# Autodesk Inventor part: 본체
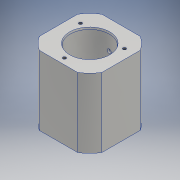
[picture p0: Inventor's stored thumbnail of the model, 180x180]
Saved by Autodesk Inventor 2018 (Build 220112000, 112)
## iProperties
Created: 2020-02
Part Number: 본체
Material: 알루미늄 6061
Document SubType Name: Modeling
Designer: Administrator
Density: 2.7 g/cm^3
Appearance: 알루미늄 - 평지
Mass: 538.447 g
Surface Area: 342.316 cm^2
Volume: 199.425 cm^3
Author: Administrator
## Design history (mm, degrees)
sketch "스케치1"
  geometry: L1 (-19.551, -32)-(19.551, -32); L2 (32, -19.551)-(32, 19.551); L3 (19.551, 32)-(-19.551, 32); L4 (-32, 19.551)-(-32, -19.551); L5 (-32, -32)-(32, 32); L6 (32, -32)-(-32, 32); A1 r 37.5 centre (0, 0) between (-19.551, 32) and (-32, 19.551); A2 r 37.5 centre (0, 0) between (-32, -19.551) and (-19.551, -32); A3 r 37.5 centre (0, 0) between (19.551, -32) and (32, -19.551); A4 r 37.5 centre (0, 0) between (32, 19.551) and (19.551, 32); 1 further point
  constraints: 12 end point, 8 point on circle, 4 centre point, 2 midpoint, 2 parallel, 2 perpendicular, 1 coincident, 1 horizontal
  dimensions: "d1" = 64 distance of L5.end L6.end; "d2" = 64 distance of L6.start L5.end; "d3" = 37.5 radius of A4; "d4" = 37.5 radius of A3; "d5" = 37.5 radius of A2; "d6" = 37.5 radius of A1; "d7" = 45 deg angle of L6 L2; "d8" = 64 distance between parallel lines of L2 L4; "d9" = 64 distance between parallel lines of L3 L1; "d10" = 32 distance from line of point (0, 0) L2; "d11" = 32 distance from line of point (0, 0) L3; "d12" = 0 distance from line of L5.end L2; "d13" = 64 distance from line of L5.start L2
extrude "돌출1" new body sketch "스케치1" distance "d14" = 71; taper "d15" = 0 deg
sketch "스케치2"
  geometry: C1 r 14 at (0, 0); 1 further point
  constraints: 1 centre point, 1 coincident
  dimensions: "d16" = 28 diameter of C1
extrude "돌출2" join sketch "스케치2" distance "d17" = 12; taper "d18" = 0 deg
sketch "스케치3"
  geometry: C1 r 20 at (0, 0); 1 further point
  constraints: 1 centre point, 1 coincident
  dimensions: "d19" = 40 diameter of C1
extrude "돌출3" cut sketch "스케치3" distance "d20" = 62; taper "d21" = 0 deg
sketch "스케치4"
  geometry: C1 r 2 at (0, 0); 1 further point
  constraints: 1 centre point, 1 coincident
  dimensions: "d22" = 4 diameter of C1
extrude "돌출4" cut sketch "스케치4" distance "d23" = 62; taper "d24" = 0 deg
sketch "스케치5"
  geometry: C1 r 2 at (0, 0) reference; 2 further points
  constraints: 1 coincident
hole "구멍1" sketch "스케치5" at (0, 0) diameter "d25" = 8.376; stored, may be unused: countersink angle "d29" = 90 deg, drill point angle "d31" = 118 deg; dims "d26" = 14, "d27" = 4, "d28" = 2, "d30" = 17
sketch "스케치6"
  geometry: L1 (39.102, -71)-(0, -71) reference; L2 (-12.449, 0)-(-12.449, -71) reference; C1 r 2 at (19.551, -54); 1 further point
  constraints: 1 centre point
  dimensions: "d32" = 17 distance from line of L1 C1.centre; "d33" = 32 distance from line of L2 C1.centre; "d34" = 4 diameter of C1
extrude "돌출5" cut sketch "스케치6" distance "d35" = 20; taper "d36" = 0 deg
sketch "스케치7"
  geometry: C1 r 2 at (19.551, -54) reference; 2 further points
  constraints: 1 coincident
hole "구멍2" sketch "스케치7" at (19.551, -54) diameter "d37" = 8.376; stored, may be unused: countersink angle "d41" = 90 deg, drill point angle "d43" = 118 deg; dims "d38" = 6, "d39" = 4, "d40" = 2, "d42" = 9
sketch "스케치8"
  geometry: C1 r 2 at (0, 0) reference; A1 r 26 centre (0, 0) between (0, 26) and (26, 0); 3 further points
  constraints: 4 point on circle, 1 centre point, 1 coincident
  dimensions: "d44" = 52 diameter of A1
hole "구멍3" sketch "스케치8" at (0, 26), (26, 0), (0, -26), (-26, 0) diameter "d45" = 3.242; stored, may be unused: countersink angle "d49" = 90 deg, drill point angle "d51" = 118 deg; dims "d46" = 10, "d47" = 4, "d48" = 2, "d50" = 12
sketch "스케치10"
  geometry: L1 (0, 26)-(0, -26); L2 (0, 0)-(22.517, 13); L3 (0, 0)-(-22.517, 13); C1 r 2 at (0, 0) reference; C2 r 1.621 at (0, 26) reference; C3 r 4.188 at (0, 0) reference; C4 r 14 at (0, 0) reference; A1 r 26 centre (0, 0) between (0, -26) and (-22.517, 13); 4 further points
  constraints: 6 end point, 4 coincident, 3 point on circle, 1 centre point, 1 vertical
  dimensions: "d66" = 52 diameter of A1; "d67" = 60 deg angle of L1 L2; "d68" = 60 deg angle of L1 L3
hole "구멍5" sketch "스케치10" at (-22.517, 13), (22.517, 13), (0, -26) diameter "d69" = 3.242; stored, may be unused: countersink angle "d73" = 90 deg, drill point angle "d75" = 118 deg; dims "d70" = 10, "d71" = 4, "d72" = 2, "d74" = 12
sketch "스케치11"
  geometry: L1 (20, 71)-(20, 9) reference; L2 (20, 71)-(20, 69.2); L3 (20, 69.2)-(20.482, 71); L4 (-20, 71)-(20, 71) reference; L5 (20, 71)-(20.482, 71); L6 (32, 71)-(19.551, 71) reference; L7 (0, 81.964)-(0, -65.316); 1 further point
  constraints: 8 end point, 3 point on line, 1 vertical
  dimensions: "d76" = 1.8 distance of L2.start L2.end; "d77" = 15 deg angle of L1 L3
revolve "회전1" sketch "스케치11" stored, may be unused: angle "d78" = 90 deg
chamfer "모따기1" distance "d79" = 1; stored, may be unused: second distance "d80" = 2, angle "d81" = 45 deg
sketch "스케치12"
  geometry: L1 (0, 0)-(39.102, 0) reference; 3 further points
  constraints: 1 midpoint, 1 vertical alignment, 1 other
  dimensions: "d82" = 20 distance from line of L1 point (19.551, -20)
feature "엠보싱1" sketch "스케치12" dims "d2" = 64, "d83" = 0.5, "d84" = 0
node "솔리드1"
other parameters: "d0" = 75
